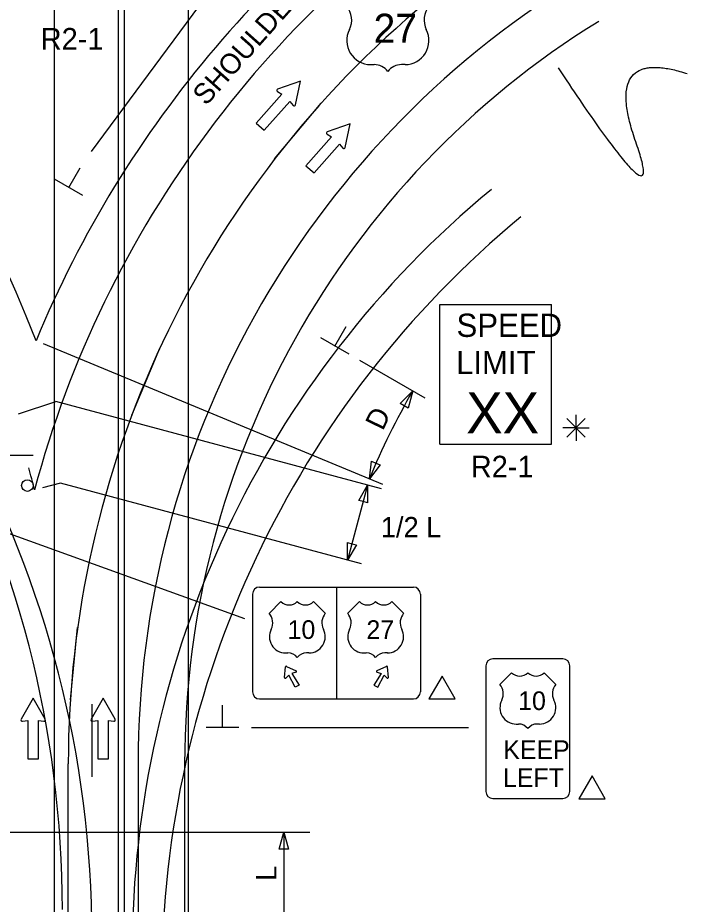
# Model space of a CAD drawing. Extents: x 16284 to 18468, y 5417 to 6974.
# Drawn here: x 16931.8 to 17161.9, y 6516.4 to 6821.2 of the extents above; entities that cross this region are included whole.
import ezdxf

# ---------------------------------------------------------------- set-up
doc = ezdxf.new("R2010")
doc.units = 0
for name, color, linetype in [('ALI_LEGAL_EX', 7, 'Continuous'), ('MT_SCRATCH_LEVEL_E', 7, 'Continuous'), ('PAVT_EDGE_EX', 7, 'Continuous'), ('TRAFFIC_SIGNS_PR', 7, 'Continuous'), ('TYPICAL_EX', 7, 'Continuous'), ('TYPICAL_TEXT_DIMEN_PR', 7, 'Continuous')]:
    doc.layers.add(name, color=color, linetype=linetype)

msp = doc.modelspace()

# ---------------------------------------------------------------- linework, layer by layer
at = {"layer": 'ALI_LEGAL_EX'}
for p, q in [((16944.3, 6974.12), (16944.3, 6155.98)), ((16968.3, 6974.12), (16968.3, 6155.98)), ((16966.29, 6836.53), (16966.29, 5997.6)), ((16990.29, 6836.53), (16990.29, 5997.6)), ((16949.13, 6287.02), (16949.13, 6564.7))]:
    msp.add_line(p, q, dxfattribs=at)
for points in [[(17020.02, 6772.64), (17036.07, 6791.8)], [(16970.92, 6684.51), (16980.56, 6707.58)], [(16949.84, 6586.69), (16952.34, 6611.56)], [(16957.27, 6585.13), (16957.27, 6560.13)]]:
    msp.add_lwpolyline(points, dxfattribs=at)
for centre, radius, start, end in [((17289.13, 6564.7), 340, 129.5666, 180), ((16583.12, 6514.52), 364, 0, 57.2958), ((16593.27, 6505.1), 364, 0, 57.2958), ((17311.12, 6500.03), 340, 129.5666, 180), ((17321.27, 6490.61), 340, 129.5666, 180)]:
    msp.add_arc(centre, radius, start, end, dxfattribs=at)
at = {"layer": 'MT_SCRATCH_LEVEL_E'}
for p, q in [((17028.96, 6799.34), (17021.08, 6796.66)), ((17027.25, 6791.17), (17028.96, 6799.34)), ((17022.52, 6794.88), (17013.72, 6784.97)), ((17020.99, 6795.82), (17022.52, 6794.88)), ((17016.51, 6782.48), (17025.32, 6792.39)), ((17025.32, 6792.39), (17026.44, 6790.98)), ((17013.72, 6784.97), (17016.51, 6782.48)), ((17046.05, 6784.68), (17038.16, 6782)), ((17044.34, 6776.51), (17046.05, 6784.68)), ((17039.61, 6780.22), (17030.8, 6770.31)), ((17038.07, 6781.17), (17039.61, 6780.22)), ((17033.6, 6767.83), (17042.4, 6777.74)), ((17042.4, 6777.74), (17043.52, 6776.32)), ((17030.8, 6770.31), (17033.6, 6767.83)), ((16937.03, 6587.21), (16932.92, 6579.97)), ((16941.18, 6579.97), (16937.03, 6587.21)), ((16961.09, 6587.21), (16956.98, 6579.97)), ((16965.24, 6579.97), (16961.09, 6587.21)), ((16933.41, 6579.29), (16935.18, 6579.6)), ((16935.18, 6579.6), (16935.18, 6566.35)), ((16938.92, 6566.35), (16938.92, 6579.6)), ((16938.92, 6579.6), (16940.7, 6579.29)), ((16957.46, 6579.29), (16959.24, 6579.6)), ((16959.24, 6579.6), (16959.24, 6566.35)), ((16962.98, 6566.35), (16962.98, 6579.6)), ((16962.98, 6579.6), (16964.76, 6579.29)), ((16935.18, 6566.35), (16938.92, 6566.35)), ((16959.24, 6566.35), (16962.98, 6566.35))]:
    msp.add_line(p, q, dxfattribs=at)
for centre, start, end in [((17021.24, 6796.22), 108.8028, 238.3418), ((17026.8, 6791.28), 218.4141, 348.1511), ((17038.32, 6781.56), 108.8028, 238.3418), ((17043.88, 6776.62), 218.4141, 348.1511), ((16933.33, 6579.75), 150.4248, 279.9638), ((16940.77, 6579.75), 260.0362, 29.7731), ((16957.39, 6579.75), 150.4248, 279.9638), ((16964.83, 6579.75), 260.0362, 29.7731)]:
    msp.add_arc(centre, 0.463, start, end, dxfattribs=at)
at = {"layer": 'PAVT_EDGE_EX'}
for p, q in [((16973.13, 6564.7), (16973.13, 6289.11)), ((16989.13, 6564.7), (16989.13, 6289.11))]:
    msp.add_line(p, q, dxfattribs=at)
for centre, radius, start, end in [((16561.13, 6564.7), 404, 21.0961, 61.7914), ((17289.13, 6564.7), 380, 121.7103, 157.5011), ((17289.13, 6564.7), 364, 121.7103, 165.0045), ((17289.13, 6564.7), 316, 121.7103, 180), ((17289.13, 6564.7), 300, 121.7103, 180), ((16561.13, 6564.7), 388, 14.0482, 15.2048), ((17289.13, 6564.7), 300, 180, 180.00000277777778)]:
    msp.add_arc(centre, radius, start, end, dxfattribs=at)
at = {"layer": 'TRAFFIC_SIGNS_PR'}
for p, q in [((17076.81, 6722.57), (17115.21, 6722.57)), ((17076.81, 6674.57), (17076.81, 6722.57)), ((17115.21, 6674.57), (17115.21, 6722.57)), ((17076.81, 6674.57), (17115.21, 6674.57)), ((17014.89, 6625.42), (17067.75, 6625.42)), ((17041.32, 6625.42), (17041.32, 6586.97)), ((17012.48, 6623.02), (17012.48, 6589.37)), ((17070.15, 6623.02), (17070.15, 6589.37)), ((17119.12, 6600.78), (17095.08, 6600.78)), ((17023.47, 6594.33), (17023.76, 6597.96)), ((17024.13, 6598.17), (17027.41, 6596.6)), ((17058.5, 6598.17), (17055.22, 6596.6)), ((17059.16, 6594.33), (17058.88, 6597.96)), ((17092.68, 6598.37), (17092.68, 6555.12)), ((17121.52, 6555.12), (17121.52, 6598.37)), ((17014.89, 6586.97), (17067.75, 6586.97)), ((17095.08, 6552.72), (17119.12, 6552.72))]:
    msp.add_line(p, q, dxfattribs=at)
for points in [[(17027.37, 6596.12), (17025.96, 6595.73), (17028.48, 6591.74), (17027.15, 6590.98), (17024.96, 6595.15), (17023.92, 6594.12)], [(17055.26, 6596.12), (17056.67, 6595.73), (17054.15, 6591.74), (17055.49, 6590.98), (17057.68, 6595.15), (17058.72, 6594.12)]]:
    msp.add_lwpolyline(points, dxfattribs=at)
msp.add_circle((16935.07, 6660.34), 2, dxfattribs=at)
for centre, radius, start, end in [((17014.88, 6623.02), 2.4, 90, 180), ((17014.88, 6623.02), 2.4, 90, 180), ((17067.75, 6623.02), 2.4, 0, 90), ((17095.09, 6598.37), 2.4, 90, 180), ((17119.12, 6598.37), 2.4, 0, 90), ((17024.02, 6597.94), 0.261, 64.4823, 175.5177), ((17027.3, 6596.37), 0.261, 285.9885, 64.4823), ((17055.34, 6596.37), 0.261, 115.5177, 254.0115), ((17058.62, 6597.94), 0.261, 4.4823, 115.5177), ((17023.73, 6594.31), 0.261, 175.5177, 314.0115), ((17058.9, 6594.31), 0.261, 225.9885, 4.4823), ((17014.88, 6589.37), 2.4, 180, 270), ((17067.75, 6589.37), 2.4, 270, 0), ((17095.09, 6555.12), 2.4, 180, 270), ((17119.12, 6555.12), 2.4, 270, 0)]:
    msp.add_arc(centre, radius, start, end, dxfattribs=at)
at = {"layer": 'TYPICAL_EX'}
for p, q in [((17053.08, 6805.06), (17054.25, 6805.06)), ((17064.88, 6805.06), (17063.7, 6805.06)), ((17018.24, 6616.41), (17022.24, 6620.41)), ((17037.46, 6616.41), (17033.46, 6620.41)), ((17045.17, 6616.41), (17049.18, 6620.41)), ((17064.4, 6616.41), (17060.39, 6620.41)), ((17023.84, 6602.78), (17024.64, 6602.78)), ((17031.86, 6602.78), (17031.06, 6602.78)), ((17050.77, 6602.78), (17051.57, 6602.78)), ((17058.8, 6602.78), (17057.99, 6602.78)), ((17097.49, 6591.97), (17101.49, 6595.97)), ((17116.71, 6591.97), (17112.71, 6595.97)), ((17103.09, 6578.34), (17103.89, 6578.34)), ((17111.11, 6578.34), (17110.31, 6578.34))]:
    msp.add_line(p, q, dxfattribs=at)
for centre, radius, start, end in [((17039.24, 6820.4), 7.31, 333.0977, 40.1936), ((17078.72, 6820.4), 7.31, 139.8064, 206.9023), ((17053.09, 6813.31), 8.24, 152.6698, 269.9013), ((17064.87, 6813.31), 8.24, 270.0987, 27.3302), ((17054.27, 6799.16), 5.91, 37.1038, 90.1385), ((17063.69, 6799.16), 5.91, 89.8615, 142.8962), ((17025.05, 6623.33), 4.05, 226.1404, 313.8596), ((17030.66, 6623.33), 4.05, 226.1404, 313.8596), ((17051.98, 6623.33), 4.05, 226.1404, 313.8596), ((17057.59, 6623.33), 4.05, 226.1404, 313.8596), ((17014.44, 6613.2), 4.97, 333.0977, 40.1936), ((17041.26, 6613.2), 4.97, 139.8064, 206.9023), ((17041.38, 6613.2), 4.97, 333.0977, 40.1936), ((17068.19, 6613.2), 4.97, 139.8064, 206.9023), ((17023.85, 6608.38), 5.6, 152.6698, 269.9013), ((17031.85, 6608.38), 5.6, 270.0987, 27.3302), ((17050.78, 6608.38), 5.6, 152.6698, 269.9013), ((17058.78, 6608.38), 5.6, 270.0987, 27.3302), ((17024.65, 6598.77), 4.01, 37.1038, 90.1385), ((17031.05, 6598.77), 4.01, 89.8615, 142.8962), ((17051.58, 6598.77), 4.01, 37.1038, 90.1385), ((17057.98, 6598.77), 4.01, 89.8615, 142.8962), ((17104.3, 6598.89), 4.05, 226.1404, 313.8596), ((17109.9, 6598.89), 4.05, 226.1404, 313.8596), ((17093.69, 6588.76), 4.97, 333.0977, 40.1936), ((17120.51, 6588.76), 4.97, 139.8064, 206.9023), ((17103.1, 6583.94), 5.6, 152.6698, 269.9013), ((17111.1, 6583.94), 5.6, 270.0987, 27.3302), ((17103.9, 6574.33), 4.01, 37.1038, 90.1385), ((17110.3, 6574.33), 4.01, 89.8615, 142.8962)]:
    msp.add_arc(centre, radius, start, end, dxfattribs=at)
at = {"layer": 'TYPICAL_TEXT_DIMEN_PR'}
for p, q in [((16957.13, 6775.18), (17013.42, 6851.3)), ((16949.29, 6762.86), (16953.18, 6769.6)), ((16954.16, 6760.04), (16944.42, 6765.67)), ((17040.79, 6708.3), (17044.68, 6715.04)), ((17057.24, 6660.74), (16940.65, 6709.03)), ((17045.66, 6705.49), (17035.92, 6711.11)), ((17071.84, 6690.34), (17049.33, 6703.35)), ((17063.22, 6688.55), (17067.51, 6692.84)), ((17067.51, 6692.84), (17065.94, 6686.98)), ((16932.03, 6685.02), (16944.83, 6689.18)), ((17056.82, 6659.18), (16944.83, 6689.18)), ((17064.58, 6687.77), (17063.22, 6688.55)), ((17065.94, 6686.98), (17064.58, 6687.77)), ((17123.67, 6680.16), (17123.67, 6684.62)), ((17120.48, 6683.35), (17126.85, 6676.97)), ((17126.85, 6683.35), (17120.48, 6676.97)), ((17123.67, 6680.16), (17119.13, 6680.16)), ((17123.67, 6680.16), (17126.85, 6680.16)), ((17123.67, 6680.16), (17128.14, 6680.16)), ((17123.67, 6680.16), (17123.67, 6675.66)), ((16937.12, 6670.66), (16925.87, 6670.66)), ((17052.62, 6662.66), (17053.41, 6668.67)), ((17056.31, 6667.47), (17052.62, 6662.66)), ((17053.41, 6668.67), (17054.86, 6668.07)), ((17054.86, 6668.07), (17056.31, 6667.47)), ((16933.36, 6661.39), (16933.36, 6661.38)), ((16946.44, 6661.11), (16940.28, 6659.57)), ((17049.91, 6633.39), (16946.44, 6661.11)), ((17052.03, 6660.46), (17045.12, 6634.68)), ((17048.99, 6655.21), (17052.03, 6660.46)), ((17052.03, 6660.46), (17052.03, 6654.39)), ((17050.51, 6654.8), (17048.99, 6655.21)), ((17052.03, 6654.39), (17050.51, 6654.8)), ((16927.57, 6644.26), (17009.73, 6614.66)), ((17045.12, 6634.68), (17045.12, 6640.75)), ((17045.12, 6640.75), (17046.64, 6640.34)), ((17048.15, 6639.93), (17045.12, 6634.68)), ((17046.64, 6640.34), (17048.15, 6639.93)), ((17002.15, 6577.09), (17002.15, 6584.88)), ((17007.77, 6577.09), (16996.52, 6577.09)), ((17012.13, 6577.09), (17086.74, 6577.09)), ((16928.89, 6541.14), (17032.15, 6541.14)), ((17021.67, 6535.28), (17023.24, 6541.14)), ((17023.24, 6541.14), (17023.24, 6509.03)), ((17023.24, 6541.14), (17024.81, 6535.28)), ((17023.24, 6535.28), (17021.67, 6535.28)), ((17024.81, 6535.28), (17023.24, 6535.28))]:
    msp.add_line(p, q, dxfattribs=at)
for points in [[(17077.63, 6594.84), (17073.1, 6587.01), (17082.15, 6587.01)], [(17129.19, 6560.48), (17124.66, 6552.65), (17133.71, 6552.65)]]:
    msp.add_lwpolyline(points, close=True, dxfattribs=at)
msp.add_arc((17289.13, 6564.7), 256, 149.9625, 157.5013, dxfattribs=at)
msp.add_open_spline([(17117.51, 6804), (17155.75, 6745.82), (17132.53, 6811.53), (17161.89, 6801.95)], degree=2, dxfattribs=at)

# ---------------------------------------------------------------- texts
at = {"layer": 'TRAFFIC_SIGNS_PR'}
for s, height, p in [('R2-1', 7.44, (16939.67, 6810.21)), ('SPEED', 8, (17082.58, 6711.44)), ('LIMIT', 8, (17082.42, 6698.64)), ('XX', 14.031, (17085.92, 6678.33)), ('R2-1', 7.44, (17087.49, 6663.13)), ('10', 6.408, (17024.51, 6607.6)), ('27', 6.408, (17051.61, 6607.6)), ('10', 6.408, (17103.76, 6583.15)), ('KEEP', 6.408, (17098.63, 6566.33)), ('LEFT', 6.408, (17098.54, 6556.72))]:
    msp.add_text(s, height=height, dxfattribs=at).set_placement(p)
at = {"layer": 'TYPICAL_EX'}
msp.add_text('27', height=10, dxfattribs=at).set_placement((17054.09, 6812.55))
at = {"layer": 'TYPICAL_TEXT_DIMEN_PR'}
for s, rotation, p in [('SHOULDER', 48.378, (16996.49, 6790.64)), ('D', 63.7334, (17057.2, 6678.9)), ('L', 90, (17020.68, 6524.44))]:
    msp.add_text(s, height=7, rotation=rotation, dxfattribs=at).set_placement(p)
msp.add_text('1/2 L', height=7, dxfattribs=at).set_placement((17056.56, 6642.53))

doc.saveas('drawing.dxf')
